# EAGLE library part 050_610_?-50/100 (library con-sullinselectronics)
.050 DIP EDGE CARD CONNECTOR .050 [1.27mm] CONTACT CENTERS .610" INSULATEOR HEIGHT Source: .050 DIP EDGE CARD.pdf
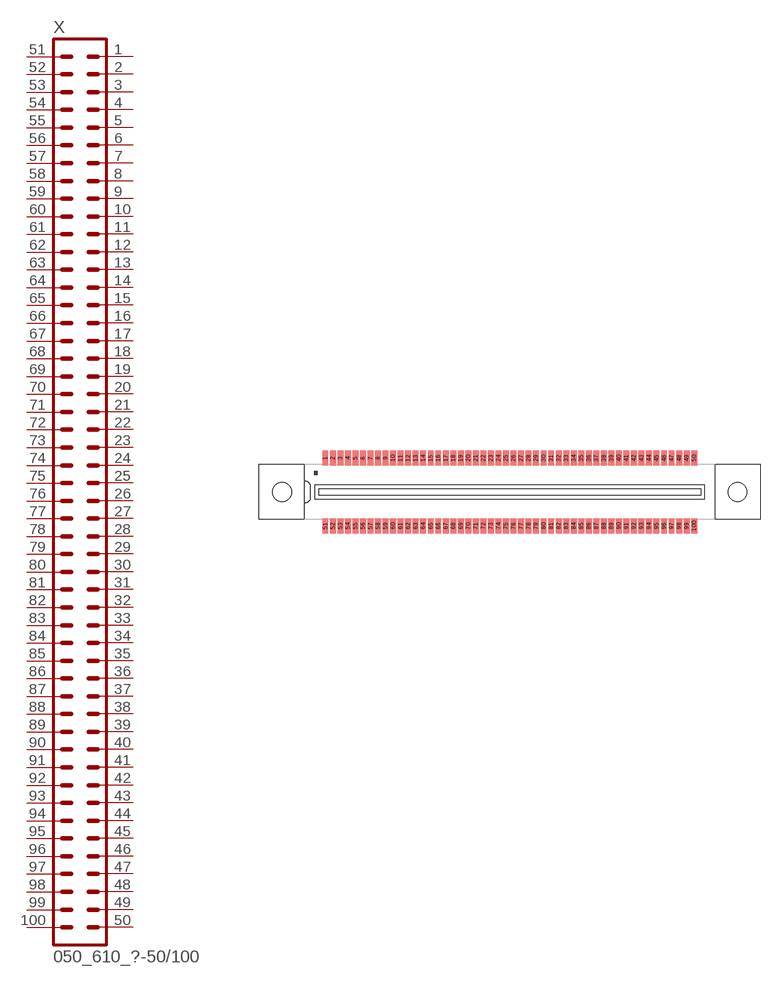
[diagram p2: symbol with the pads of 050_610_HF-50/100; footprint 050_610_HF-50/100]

Designator prefix X

## 050_610_HF-50/100 (OC_FARNELL: unknown; OC_NEWARK: unknown)  [050_610_HF-50/100]
1  1  pas
2  2  pas
3  3  pas
4  4  pas
5  5  pas
6  6  pas
7  7  pas
8  8  pas
9  9  pas
10  10  pas
11  11  pas
12  12  pas
13  13  pas
14  14  pas
15  15  pas
16  16  pas
17  17  pas
18  18  pas
19  19  pas
20  20  pas
21  21  pas
22  22  pas
23  23  pas
24  24  pas
25  25  pas
26  26  pas
27  27  pas
28  28  pas
29  29  pas
30  30  pas
31  31  pas
32  32  pas
33  33  pas
34  34  pas
35  35  pas
36  36  pas
37  37  pas
38  38  pas
39  39  pas
40  40  pas
41  41  pas
42  42  pas
43  43  pas
44  44  pas
45  45  pas
46  46  pas
47  47  pas
48  48  pas
49  49  pas
50  50  pas
51  51  pas
52  52  pas
53  53  pas
54  54  pas
55  55  pas
56  56  pas
57  57  pas
58  58  pas
59  59  pas
60  60  pas
61  61  pas
62  62  pas
63  63  pas
64  64  pas
65  65  pas
66  66  pas
67  67  pas
68  68  pas
69  69  pas
70  70  pas
71  71  pas
72  72  pas
73  73  pas
74  74  pas
75  75  pas
76  76  pas
77  77  pas
78  78  pas
79  79  pas
80  80  pas
81  81  pas
82  82  pas
83  83  pas
84  84  pas
85  85  pas
86  86  pas
87  87  pas
88  88  pas
89  89  pas
90  90  pas
91  91  pas
92  92  pas
93  93  pas
94  94  pas
95  95  pas
96  96  pas
97  97  pas
98  98  pas
99  99  pas
100  100  pas

## Footprint 050_610_HF-50/100 (pad centres in mm)
.050 DIP EDGE CARD CONNECTOR SURFACE MOUNT .050 [1.27mm] CONTACT CENTERS .610" INSULATEOR HEIGHT Source: .050 DIP EDGE CARD.pdf
smd 1 x 2.5: 1 -31.115,5.715; 2 -29.845,5.715; 3 -28.575,5.715; 4 -27.305,5.715; 5 -26.035,5.715; 6 -24.765,5.715; 7 -23.495,5.715; 8 -22.225,5.715; 9 -20.955,5.715; 10 -19.685,5.715; 11 -18.415,5.715; 12 -17.145,5.715; 13 -15.875,5.715; 14 -14.605,5.715; 15 -13.335,5.715; 16 -12.065,5.715; 17 -10.795,5.715; 18 -9.525,5.715; 19 -8.255,5.715; 20 -6.985,5.715; 21 -5.715,5.715; 22 -4.445,5.715; 23 -3.175,5.715; 24 -1.905,5.715; 25 -0.635,5.715; 26 0.635,5.715; 27 1.905,5.715; 28 3.175,5.715; 29 4.445,5.715; 30 5.715,5.715; 31 6.985,5.715; 32 8.255,5.715; 33 9.525,5.715; 34 10.795,5.715; 35 12.065,5.715; 36 13.335,5.715; 37 14.605,5.715; 38 15.875,5.715; 39 17.145,5.715; 40 18.415,5.715; 41 19.685,5.715; 42 20.955,5.715; 43 22.225,5.715; 44 23.495,5.715; 45 24.765,5.715; 46 26.035,5.715; 47 27.305,5.715; 48 28.575,5.715; 49 29.845,5.715; 50 31.115,5.715; 51 -31.115,-5.715; 52 -29.845,-5.715; 53 -28.575,-5.715; 54 -27.305,-5.715; 55 -26.035,-5.715; 56 -24.765,-5.715; 57 -23.495,-5.715; 58 -22.225,-5.715; 59 -20.955,-5.715; 60 -19.685,-5.715; 61 -18.415,-5.715; 62 -17.145,-5.715; 63 -15.875,-5.715; 64 -14.605,-5.715; 65 -13.335,-5.715; 66 -12.065,-5.715; 67 -10.795,-5.715; 68 -9.525,-5.715; 69 -8.255,-5.715; 70 -6.985,-5.715; 71 -5.715,-5.715; 72 -4.445,-5.715; 73 -3.175,-5.715; 74 -1.905,-5.715; 75 -0.635,-5.715; 76 0.635,-5.715; 77 1.905,-5.715; 78 3.175,-5.715; 79 4.445,-5.715; 80 5.715,-5.715; 81 6.985,-5.715; 82 8.255,-5.715; 83 9.525,-5.715; 84 10.795,-5.715; 85 12.065,-5.715; 86 13.335,-5.715; 87 14.605,-5.715; 88 15.875,-5.715; 89 17.145,-5.715; 90 18.415,-5.715; 91 19.685,-5.715; 92 20.955,-5.715; 93 22.225,-5.715; 94 23.495,-5.715; 95 24.765,-5.715; 96 26.035,-5.715; 97 27.305,-5.715; 98 28.575,-5.715; 99 29.845,-5.715; 100 31.115,-5.715
hole 3.18 at -38.43,0
hole 3.18 at 38.43,0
